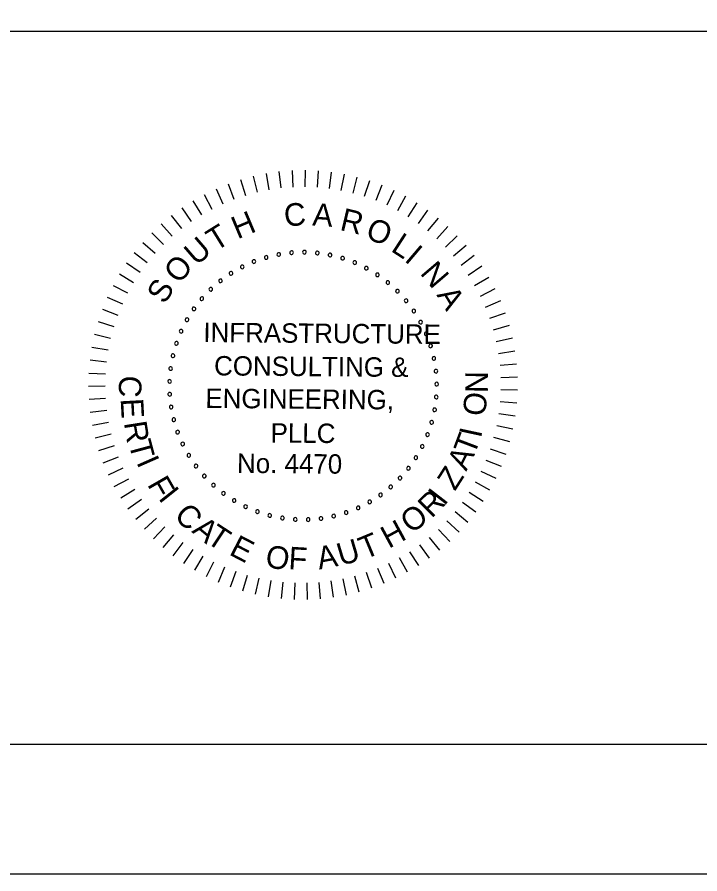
# Model space of a CAD drawing. Extents: x -50.5 to -14.4, y -5.1 to 16.9.
# Drawn here: x -25.289 to -22.655, y -5.066 to -1.762 of the extents above; entities that cross this region are included whole.
import ezdxf

# ---------------------------------------------------------------- set-up
doc = ezdxf.new("R2010")
doc.units = 0
for name, color, linetype in [('BR_BORDER LINES', 7, 'Continuous'), ('BR_TEXT', 7, 'Continuous'), ('Level 31', 7, 'Continuous')]:
    doc.layers.add(name, color=color, linetype=linetype)

msp = doc.modelspace()

# ---------------------------------------------------------------- linework, layer by layer
at = {"layer": 'BR_BORDER LINES'}
for p, q in [((-27.8847, -1.8161), (-22.5195, -1.8161)), ((-48.6853, -4.5662), (-15.0192, -4.5662))]:
    msp.add_line(p, q, dxfattribs=at)
at = {"layer": 'BR_TEXT'}
for p, q in [((-24.3783, -2.3754), (-24.3634, -2.4373)), ((-24.3289, -2.3651), (-24.3178, -2.4278)), ((-24.2789, -2.3579), (-24.2717, -2.4212)), ((-24.2286, -2.3538), (-24.2252, -2.4174)), ((-24.1781, -2.3527), (-24.1786, -2.4164)), ((-24.1277, -2.3548), (-24.1321, -2.4183)), ((-24.0774, -2.3599), (-24.0857, -2.423)), ((-24.0276, -2.368), (-24.0397, -2.4305)), ((-24.4748, -2.4048), (-24.4525, -2.4644)), ((-24.427, -2.3886), (-24.4084, -2.4495)), ((-23.9784, -2.3792), (-23.9943, -2.4408)), ((-23.9299, -2.3933), (-23.9495, -2.4539)), ((-23.8824, -2.4104), (-23.9057, -2.4696)), ((-24.5216, -2.4238), (-24.4957, -2.482)), ((-23.836, -2.4303), (-23.8629, -2.488)), ((-24.6112, -2.4703), (-24.5784, -2.5249)), ((-24.5671, -2.4457), (-24.5377, -2.5022)), ((-23.7909, -2.453), (-23.8213, -2.509)), ((-24.6537, -2.4975), (-24.6176, -2.55)), ((-23.7473, -2.4785), (-23.781, -2.5325)), ((-23.7054, -2.5065), (-23.7423, -2.5584)), ((-24.6944, -2.5273), (-24.6553, -2.5775)), ((-23.6652, -2.5371), (-23.7052, -2.5866)), ((-24.7333, -2.5595), (-24.6911, -2.6072)), ((-23.6269, -2.57), (-23.6699, -2.617)), ((-24.7701, -2.5941), (-24.7251, -2.6391)), ((-23.5907, -2.6052), (-23.6365, -2.6495)), ((-24.8048, -2.6308), (-24.7571, -2.673)), ((-23.5568, -2.6426), (-23.6051, -2.684)), ((-24.8372, -2.6695), (-24.787, -2.7087)), ((-23.5252, -2.6819), (-23.576, -2.7204)), ((-24.8671, -2.7102), (-24.8147, -2.7463)), ((-23.496, -2.7232), (-23.549, -2.7584)), ((-24.8945, -2.7526), (-24.84, -2.7854)), ((-23.4694, -2.7661), (-23.5245, -2.798)), ((-24.9193, -2.7966), (-24.8628, -2.826)), ((-23.4455, -2.8105), (-23.5024, -2.839)), ((-24.9413, -2.842), (-24.8832, -2.8679)), ((-23.4243, -2.8564), (-23.4829, -2.8814)), ((-24.9605, -2.8886), (-24.9009, -2.911)), ((-23.406, -2.9034), (-23.466, -2.9248)), ((-24.9769, -2.9364), (-24.916, -2.9551)), ((-23.3905, -2.9515), (-23.4517, -2.9691)), ((-24.9903, -2.9851), (-24.9284, -3)), ((-23.3781, -3.0004), (-23.4402, -3.0143)), ((-25.0007, -3.0345), (-24.938, -3.0456)), ((-23.3686, -3.05), (-23.4315, -3.0601)), ((-25.0081, -3.0844), (-24.9448, -3.0917)), ((-23.3622, -3.1), (-23.4255, -3.1063)), ((-25.0124, -3.1347), (-24.9488, -3.1382)), ((-23.3588, -3.1504), (-23.4224, -3.1528)), ((-25.0136, -3.1852), (-24.95, -3.1847)), ((-23.3585, -3.2009), (-23.4221, -3.1994)), ((-25.0118, -3.2356), (-24.9483, -3.2313)), ((-23.3613, -3.2513), (-23.4247, -3.2459)), ((-25.0069, -3.2859), (-24.9438, -3.2777)), ((-23.3671, -3.3014), (-23.4301, -3.2922)), ((-24.999, -3.3357), (-24.9364, -3.3237)), ((-24.988, -3.385), (-24.9263, -3.3692)), ((-23.376, -3.3511), (-23.4384, -3.3381)), ((-23.388, -3.4002), (-23.4494, -3.3834)), ((-24.974, -3.4335), (-24.9134, -3.414)), ((-23.4028, -3.4484), (-23.4631, -3.4279)), ((-24.9571, -3.4811), (-24.8978, -3.4579)), ((-24.9373, -3.5276), (-24.8796, -3.5008)), ((-23.4206, -3.4957), (-23.4795, -3.4715)), ((-23.4413, -3.5417), (-23.4986, -3.514)), ((-24.9148, -3.5727), (-24.8588, -3.5425)), ((-23.4647, -3.5865), (-23.5202, -3.5553)), ((-24.8895, -3.6164), (-24.8354, -3.5828)), ((-23.4908, -3.6297), (-23.5443, -3.5952)), ((-24.8616, -3.6585), (-24.8097, -3.6217)), ((-23.5195, -3.6712), (-23.5708, -3.6335)), ((-24.8312, -3.6988), (-24.7816, -3.6589)), ((-24.7984, -3.7372), (-24.7514, -3.6943)), ((-23.5506, -3.7109), (-23.5995, -3.6702)), ((-24.7633, -3.7735), (-24.719, -3.7278)), ((-23.5841, -3.7487), (-23.6305, -3.705)), ((-24.7261, -3.8076), (-24.6846, -3.7593)), ((-23.6199, -3.7843), (-23.6635, -3.7379)), ((-24.6869, -3.8393), (-24.6484, -3.7886)), ((-23.6976, -3.8487), (-23.7352, -3.7974)), ((-23.6578, -3.8177), (-23.6985, -3.7687)), ((-24.6458, -3.8687), (-24.6105, -3.8157)), ((-23.7393, -3.8772), (-23.7737, -3.8237)), ((-24.603, -3.8954), (-24.5709, -3.8404)), ((-24.5586, -3.9195), (-24.53, -3.8626)), ((-23.7826, -3.9032), (-23.8137, -3.8476)), ((-24.5128, -3.9408), (-24.4878, -3.8823)), ((-23.8735, -3.9469), (-23.8976, -3.888)), ((-23.8274, -3.9264), (-23.855, -3.8691)), ((-24.4659, -3.9594), (-24.4444, -3.8994)), ((-24.4179, -3.975), (-24.4001, -3.9138)), ((-24.369, -3.9876), (-24.355, -3.9255)), ((-24.0182, -3.991), (-24.0312, -3.9286)), ((-23.9691, -3.9792), (-23.9859, -3.9178)), ((-23.9208, -3.9645), (-23.9413, -3.9042)), ((-24.3194, -3.9973), (-24.3092, -3.9344)), ((-24.2694, -4.0039), (-24.2631, -3.9406)), ((-24.219, -4.0075), (-24.2166, -3.9438)), ((-24.1686, -4.0079), (-24.17, -3.9443)), ((-24.1181, -4.0053), (-24.1234, -3.9419)), ((-24.068, -3.9997), (-24.0771, -3.9367))]:
    msp.add_line(p, q, dxfattribs=at)
for centre, start, end in [((-24.2797, -2.6775), 10.6038, 190.6038), ((-24.2303, -2.6708), 5.0653, 185.0653), ((-24.2303, -2.6708), 185.0653, 5.0653), ((-24.1805, -2.6689), 359.5268, 179.5268), ((-24.1805, -2.6689), 179.5268, 359.5268), ((-24.1308, -2.6718), 353.9884, 173.9884), ((-24.1308, -2.6718), 173.9884, 353.9884), ((-24.0816, -2.6795), 348.4499, 168.4499), ((-24.3754, -2.705), 21.6807, 201.6807), ((-24.3754, -2.705), 201.6807, 21.6807), ((-24.3282, -2.6889), 16.1422, 196.1422), ((-24.3282, -2.6889), 196.1422, 16.1422), ((-24.2797, -2.6775), 190.6038, 10.6038), ((-24.0816, -2.6795), 168.4499, 348.4499), ((-24.0333, -2.6919), 162.9114, 342.9114), ((-24.0333, -2.6919), 342.9114, 162.9114), ((-23.9865, -2.709), 157.373, 337.373), ((-23.9865, -2.709), 337.373, 157.373), ((-24.4208, -2.7255), 27.2191, 207.2191), ((-24.4208, -2.7255), 207.2191, 27.2191), ((-23.9415, -2.7304), 151.8345, 331.8345), ((-23.9415, -2.7304), 331.8345, 151.8345), ((-24.5046, -2.7792), 38.2961, 218.2961), ((-24.5046, -2.7792), 218.2961, 38.2961), ((-24.464, -2.7503), 32.7576, 212.7576), ((-24.464, -2.7503), 212.7576, 32.7576), ((-23.8988, -2.7561), 146.2961, 326.2961), ((-23.8988, -2.7561), 326.2961, 146.2961), ((-24.5422, -2.8119), 43.8345, 223.8345), ((-24.5422, -2.8119), 223.8345, 43.8345), ((-23.8588, -2.7858), 140.7576, 320.7576), ((-23.8588, -2.7858), 320.7576, 140.7576), ((-24.5765, -2.848), 49.373, 229.373), ((-23.8218, -2.8192), 135.2191, 315.2191), ((-23.8218, -2.8192), 315.2191, 135.2191), ((-24.5765, -2.848), 229.373, 49.373), ((-23.7883, -2.8561), 129.6807, 309.6807), ((-23.7883, -2.8561), 309.6807, 129.6807), ((-24.6072, -2.8873), 54.9114, 234.9114), ((-24.6072, -2.8873), 234.9114, 54.9114), ((-23.7584, -2.896), 124.1422, 304.1422), ((-23.7584, -2.896), 304.1422, 124.1422), ((-24.6339, -2.9293), 60.4499, 240.4499), ((-24.6339, -2.9293), 240.4499, 60.4499), ((-23.7326, -2.9386), 118.6038, 298.6038), ((-23.7326, -2.9386), 298.6038, 118.6038), ((-24.6565, -2.9738), 65.9884, 245.9884), ((-24.6565, -2.9738), 245.9884, 65.9884), ((-23.7109, -2.9835), 113.0653, 293.0653), ((-23.7109, -2.9835), 293.0653, 113.0653), ((-24.6746, -3.0202), 71.5268, 251.5268), ((-24.6746, -3.0202), 251.5268, 71.5268), ((-23.6937, -3.0302), 107.5268, 287.5268), ((-23.6937, -3.0302), 287.5268, 107.5268), ((-24.6882, -3.0681), 77.0653, 257.0653), ((-24.6882, -3.0681), 257.0653, 77.0653), ((-23.6812, -3.0785), 101.9884, 281.9884), ((-23.6812, -3.0785), 281.9884, 101.9884), ((-24.6971, -3.1172), 82.6038, 262.6038), ((-24.6971, -3.1172), 262.6038, 82.6038), ((-23.6733, -3.1277), 96.4499, 276.4499), ((-23.6733, -3.1277), 276.4499, 96.4499), ((-24.7012, -3.1668), 88.1422, 268.1422), ((-24.7012, -3.1668), 268.1422, 88.1422), ((-23.6702, -3.1774), 90.9114, 270.9114), ((-23.6702, -3.1774), 270.9114, 90.9114), ((-24.7005, -3.2167), 93.6807, 273.6807), ((-24.7005, -3.2167), 273.6807, 93.6807), ((-23.6719, -3.2272), 85.373, 265.373), ((-23.6719, -3.2272), 265.373, 85.373), ((-24.695, -3.2662), 99.2191, 279.2191), ((-24.695, -3.2662), 279.2191, 99.2191), ((-23.6784, -3.2766), 79.8345, 259.8345), ((-23.6784, -3.2766), 259.8345, 79.8345), ((-24.6848, -3.3149), 104.7576, 284.7576), ((-24.6848, -3.3149), 284.7576, 104.7576), ((-23.6896, -3.3251), 74.2961, 254.2961), ((-23.6896, -3.3251), 254.2961, 74.2961), ((-24.6699, -3.3625), 110.2961, 290.2961), ((-24.6699, -3.3625), 290.2961, 110.2961), ((-23.7055, -3.3724), 68.7576, 248.7576), ((-23.7055, -3.3724), 248.7576, 68.7576), ((-24.6504, -3.4084), 115.8345, 295.8345), ((-24.6504, -3.4084), 295.8345, 115.8345), ((-23.7259, -3.4179), 63.2191, 243.2191), ((-23.7259, -3.4179), 243.2191, 63.2191), ((-24.6267, -3.4522), 121.373, 301.373), ((-24.6267, -3.4522), 301.373, 121.373), ((-23.7506, -3.4612), 57.6807, 237.6807), ((-23.7506, -3.4612), 237.6807, 57.6807), ((-24.5988, -3.4935), 126.9114, 306.9114), ((-24.5988, -3.4935), 306.9114, 126.9114), ((-23.7793, -3.5019), 52.1422, 232.1422), ((-23.7793, -3.5019), 232.1422, 52.1422), ((-24.567, -3.5319), 132.4499, 312.4499), ((-24.567, -3.5319), 312.4499, 132.4499), ((-23.8118, -3.5396), 46.6038, 226.6038), ((-23.8118, -3.5396), 226.6038, 46.6038), ((-24.5317, -3.5671), 137.9884, 317.9884), ((-24.5317, -3.5671), 317.9884, 137.9884), ((-23.8478, -3.5741), 41.0653, 221.0653), ((-24.4932, -3.5987), 143.5268, 323.5268), ((-24.4932, -3.5987), 323.5268, 143.5268), ((-23.887, -3.6049), 35.5268, 215.5268), ((-23.887, -3.6049), 215.5268, 35.5268), ((-23.8478, -3.5741), 221.0653, 41.0653), ((-24.4518, -3.6264), 149.0653, 329.0653), ((-24.4518, -3.6264), 329.0653, 149.0653), ((-23.9289, -3.6317), 29.9884, 209.9884), ((-23.9289, -3.6317), 209.9884, 29.9884), ((-24.4079, -3.65), 154.6038, 334.6038), ((-24.4079, -3.65), 334.6038, 154.6038), ((-24.362, -3.6693), 160.1422, 340.1422), ((-24.362, -3.6693), 340.1422, 160.1422), ((-24.0196, -3.6728), 18.9114, 198.9114), ((-23.9733, -3.6545), 24.4499, 204.4499), ((-23.9733, -3.6545), 204.4499, 24.4499), ((-24.3144, -3.684), 165.6807, 345.6807), ((-24.3144, -3.684), 345.6807, 165.6807), ((-24.2656, -3.6941), 171.2191, 351.2191), ((-24.2656, -3.6941), 351.2191, 171.2191), ((-24.216, -3.6994), 356.7576, 176.7576), ((-24.216, -3.6994), 176.7576, 356.7576), ((-24.1662, -3.6999), 2.2961, 182.2961), ((-24.1662, -3.6999), 182.2961, 2.2961), ((-24.1165, -3.6956), 7.8345, 187.8345), ((-24.1165, -3.6956), 187.8345, 7.8345), ((-24.0675, -3.6865), 13.373, 193.373), ((-24.0675, -3.6865), 193.373, 13.373), ((-24.0196, -3.6728), 198.9114, 18.9114)]:
    msp.add_arc(centre, 0.00701, start, end, dxfattribs=at)
at = {"layer": 'Level 31'}
msp.add_lwpolyline([(-50.5186, -5.0661), (-14.5186, -5.0661), (-14.5186, 16.9339), (-50.5186, 16.9339)], close=True, dxfattribs=at)

# ---------------------------------------------------------------- texts
at = {"layer": 'BR_TEXT'}
for s, height, rotation, p in [('C', 0.0872, 4.7281, (-24.256, -2.5703)), ('H', 0.0872, 22.7882, (-24.4389, -2.6197)), ('A', 0.0872, 355.6981, (-24.1516, -2.5654)), ('R', 0.0872, 346.6681, (-24.0473, -2.5824)), ('O', 0.0872, 337.638, (-23.9496, -2.6122)), ('T', 0.0872, 31.8182, (-24.5237, -2.6674)), ('U', 0.0872, 40.8482, (-24.597, -2.7235)), ('L', 0.0872, 327.108, (-23.8507, -2.6626)), ('I', 0.0872, 319.578, (-23.7982, -2.7005)), ('O', 0.0872, 49.8782, (-24.664, -2.7945)), ('N', 0.0872, 310.548, (-23.7373, -2.7512)), ('S', 0.0872, 58.9083, (-24.7194, -2.8727)), ('A', 0.0872, 301.5179, (-23.6723, -2.8336)), ('INFRASTRUCTURE', 0.074771, 359.5268, (-24.5708, -3.0152)), ('CONSULTING &', 0.074771, 359.5268, (-24.5295, -3.1438)), ('N', 0.0872, 89.2085, (-23.473, -3.2124)), ('C', 0.0872, 267.025, (-24.8944, -3.1426)), ('ENGINEERING,', 0.074771, 359.5268, (-24.5631, -3.2693)), ('O', 0.0872, 83.2085, (-23.4841, -3.3038)), ('E', 0.0872, 273.025, (-24.89, -3.2342)), ('R', 0.0872, 279.025, (-24.8773, -3.3265)), ('PLLC', 0.07477, 359.5268, (-24.3114, -3.4028)), ('T', 0.0872, 69.3954, (-23.5253, -3.4556)), ('I', 0.0872, 77.9093, (-23.4996, -3.3881)), ('T', 0.0872, 285.025, (-24.8599, -3.4053)), ('I', 0.0872, 293.7713, (-24.8302, -3.4784)), ('No. 4470', 0.07477, 359.5268, (-24.441, -3.5197)), ('A', 0.0872, 63.3954, (-23.5561, -3.516)), ('Z', 0.0872, 57.3954, (-23.5999, -3.5923)), ('F', 0.0872, 299.7713, (-24.789, -3.5644)), ('I', 0.0872, 308.5268, (-24.7469, -3.6183)), ('R', 0.0872, 44.5268, (-23.6904, -3.6973)), ('I', 0.0872, 52.3339, (-23.641, -3.65)), ('C', 0.0872, 314.5268, (-24.6875, -3.6884)), ('O', 0.0872, 38.5268, (-23.7669, -3.7572)), ('A', 0.0872, 320.5268, (-24.6184, -3.747)), ('T', 0.0872, 326.5268, (-24.5639, -3.7855)), ('H', 0.0872, 28.5268, (-23.855, -3.8132)), ('E', 0.0872, 332.5268, (-24.4753, -3.8332)), ('T', 0.0872, 22.5268, (-23.9482, -3.855)), ('O', 0.0872, 350.5268, (-24.3352, -3.8821)), ('A', 0.0872, 10.5268, (-24.1239, -3.8929)), ('U', 0.0872, 16.5268, (-24.04, -3.8794)), ('F', 0.0872, 356.5268, (-24.2437, -3.8912))]:
    msp.add_text(s, height=height, rotation=rotation, dxfattribs=at).set_placement(p)

doc.saveas('drawing.dxf')
